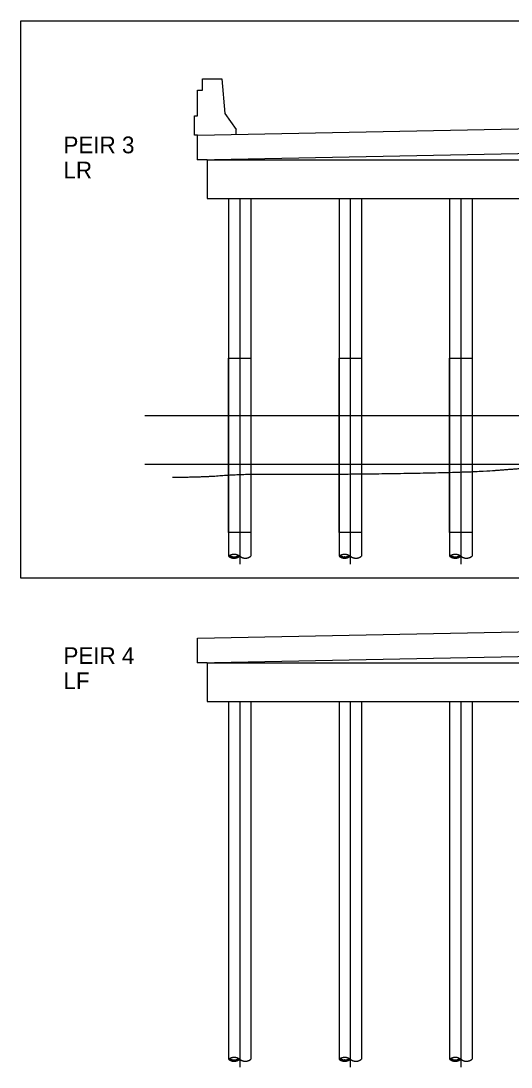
# Model space of a CAD drawing. Extents: x -8 to 159, y -47 to 10.
# Drawn here: x 49.8 to 75.3, y -47 to 7.4 of the extents above; entities that cross this region are included whole.
import ezdxf

# ---------------------------------------------------------------- set-up
doc = ezdxf.new("R2010")
doc.units = 0
for name, color, linetype in [('BR_P_Gen_Hatch', 7, 'Continuous'), ('BR_X_Gen_Ground_Slope', 7, 'Continuous'), ('BR_X_Rail_Object', 7, 'Continuous'), ('BR_X_Slab_Const_Joint', 7, 'Continuous'), ('BR_X_Slab_Object', 7, 'Continuous'), ('BR_X_Sub_Deep_Centerline', 7, 'Continuous'), ('BR_X_Sub_Object', 7, 'Continuous'), ('Default', 7, 'Continuous'), ('HY_P_Water_Edge', 7, 'Continuous')]:
    doc.layers.add(name, color=color, linetype=linetype)

msp = doc.modelspace()

# ---------------------------------------------------------------- linework, layer by layer
at = {"layer": 'BR_P_Gen_Hatch'}
for points in [[(60.566, -10.158), (61.733, -10.158), (61.733, -19.221), (60.566, -19.221)], [(66.316, -10.158), (67.483, -10.158), (67.483, -19.221), (66.316, -19.221)], [(72.066, -10.158), (73.233, -10.158), (73.233, -19.221), (72.066, -19.221)]]:
    msp.add_lwpolyline(points, close=True, dxfattribs=at)
at = {"layer": 'BR_X_Gen_Ground_Slope'}
msp.add_line((61.15, -16.221), (61.15, -19.221), dxfattribs=at)
msp.add_open_spline([(57.657, -16.344), (59.111, -16.344), (61.15, -16.188), (63.344, -16.188), (67.317, -16.188), (73.234, -16.084), (75.553, -15.906), (77.817, -15.746), (78.984, -15.688), (81.617, -15.814), (83.567, -15.688), (84.734, -15.688), (90.316, -15.589), (92.759, -15.688), (96.234, -15.688), (100.033, -15.777), (101.984, -15.688), (107.931, -15.427)], degree=2, dxfattribs=at)
at = {"layer": 'BR_X_Rail_Object'}
for p, q in [((59.212, 3.77), (59.212, 4.354)), ((59.212, 4.354), (60.212, 4.354)), ((60.212, 4.354), (60.379, 2.56)), ((58.962, 2.437), (58.962, 3.77)), ((58.962, 2.437), (58.962, 3.77)), ((58.962, 3.77), (59.212, 3.77)), ((58.795, 1.437), (58.795, 2.437)), ((58.795, 2.437), (58.962, 2.437)), ((60.379, 2.56), (60.962, 1.727)), ((60.962, 1.477), (60.962, 1.727)), ((58.962, 1.437), (58.795, 1.437))]:
    msp.add_line(p, q, dxfattribs=at)
at = {"layer": 'BR_X_Slab_Const_Joint'}
for p, q in [((59.462, 0.146), (103.087, 0.146)), ((59.462, -26), (103.087, -26))]:
    msp.add_line(p, q, dxfattribs=at)
at = {"layer": 'BR_X_Slab_Object'}
for p, q in [((58.962, 1.437), (84.317, 1.937)), ((58.962, 0.146), (58.962, 1.437)), ((58.962, 0.146), (84.317, 0.646)), ((59.462, 0.146), (58.962, 0.146)), ((58.962, -24.708), (84.317, -24.208)), ((58.962, -26), (58.962, -24.708)), ((58.962, -26), (84.317, -25.5)), ((59.462, -26), (58.962, -26))]:
    msp.add_line(p, q, dxfattribs=at)
at = {"layer": 'BR_X_Sub_Deep_Centerline'}
for p, q in [((61.15, -1.854), (61.15, -20.859)), ((66.9, -1.854), (66.9, -20.859)), ((72.65, -1.854), (72.65, -20.859)), ((61.15, -28), (61.15, -47.005)), ((66.9, -28), (66.9, -47.005)), ((72.65, -28), (72.65, -47.005))]:
    msp.add_line(p, q, dxfattribs=at)
at = {"layer": 'BR_X_Sub_Object'}
for p, q in [((59.462, 0.146), (59.462, -1.854)), ((59.462, -1.854), (103.087, -1.854)), ((60.566, -1.854), (60.566, -20.447)), ((61.733, -1.854), (61.733, -20.447)), ((66.316, -1.854), (66.316, -20.447)), ((67.483, -1.854), (67.483, -20.447)), ((72.066, -1.854), (72.066, -20.447)), ((73.233, -1.854), (73.233, -20.447)), ((59.462, -26), (59.462, -28)), ((59.462, -28), (103.087, -28)), ((60.566, -28), (60.566, -46.593)), ((61.733, -28), (61.733, -46.593)), ((66.316, -28), (66.316, -46.593)), ((67.483, -28), (67.483, -46.593)), ((72.066, -28), (72.066, -46.593)), ((73.233, -28), (73.233, -46.593))]:
    msp.add_line(p, q, dxfattribs=at)
for points in [[(60.566, -20.447), (60.624, -20.407), (60.736, -20.361), (60.817, -20.347), (60.859, -20.345), (60.887, -20.346), (60.936, -20.352), (60.976, -20.36), (61.003, -20.368), (61.047, -20.385), (61.082, -20.402), (61.11, -20.419), (61.124, -20.428), (61.139, -20.439), (61.15, -20.447), (61.169, -20.463), (61.183, -20.473), (61.194, -20.48), (61.207, -20.489), (61.231, -20.502), (61.26, -20.516), (61.277, -20.523), (61.306, -20.533), (61.338, -20.542), (61.353, -20.545), (61.375, -20.549), (61.396, -20.552), (61.42, -20.554), (61.44, -20.554), (61.481, -20.552), (61.513, -20.548), (61.545, -20.542), (61.569, -20.536), (61.593, -20.528), (61.612, -20.52), (61.633, -20.511), (61.656, -20.5), (61.673, -20.49), (61.692, -20.478), (61.713, -20.463), (61.721, -20.457), (61.733, -20.447)], [(60.566, -20.447), (60.581, -20.46), (60.602, -20.475), (60.623, -20.488), (60.645, -20.501), (60.661, -20.509), (60.686, -20.52), (60.71, -20.529), (60.737, -20.538), (60.767, -20.545), (60.79, -20.549), (60.81, -20.552), (60.83, -20.553), (60.863, -20.554), (60.892, -20.554), (60.913, -20.551), (60.939, -20.547), (60.976, -20.538), (61.005, -20.529), (61.032, -20.519), (61.055, -20.508), (61.071, -20.5), (61.094, -20.487), (61.113, -20.475), (61.127, -20.465), (61.136, -20.458), (61.15, -20.447)], [(60.628, -20.41), (60.647, -20.424), (60.671, -20.438), (60.684, -20.445), (60.699, -20.453), (60.72, -20.462), (60.741, -20.469), (60.755, -20.474), (60.78, -20.48), (60.794, -20.483), (60.814, -20.486), (60.836, -20.488), (60.861, -20.489), (60.854, -20.489), (60.872, -20.489), (60.885, -20.488), (60.908, -20.486), (60.937, -20.482), (60.954, -20.478), (60.975, -20.472), (60.989, -20.468), (61.009, -20.46), (61.02, -20.456), (61.029, -20.451), (61.039, -20.446), (61.052, -20.439), (61.063, -20.433), (61.08, -20.422), (61.086, -20.418), (61.096, -20.41)], [(66.316, -20.447), (66.374, -20.407), (66.486, -20.361), (66.567, -20.347), (66.609, -20.345), (66.637, -20.346), (66.686, -20.352), (66.726, -20.36), (66.753, -20.368), (66.797, -20.385), (66.832, -20.402), (66.86, -20.419), (66.874, -20.428), (66.889, -20.439), (66.9, -20.447), (66.919, -20.463), (66.933, -20.473), (66.944, -20.48), (66.957, -20.489), (66.981, -20.502), (67.01, -20.516), (67.027, -20.523), (67.056, -20.533), (67.088, -20.542), (67.103, -20.545), (67.125, -20.549), (67.146, -20.552), (67.17, -20.554), (67.19, -20.554), (67.231, -20.552), (67.263, -20.548), (67.295, -20.542), (67.319, -20.536), (67.343, -20.528), (67.362, -20.52), (67.383, -20.511), (67.406, -20.5), (67.423, -20.49), (67.442, -20.478), (67.463, -20.463), (67.471, -20.457), (67.483, -20.447)], [(66.316, -20.447), (66.331, -20.46), (66.352, -20.475), (66.373, -20.488), (66.395, -20.501), (66.411, -20.509), (66.436, -20.52), (66.46, -20.529), (66.487, -20.538), (66.517, -20.545), (66.54, -20.549), (66.56, -20.552), (66.58, -20.553), (66.613, -20.554), (66.642, -20.554), (66.663, -20.551), (66.689, -20.547), (66.726, -20.538), (66.755, -20.529), (66.782, -20.519), (66.805, -20.508), (66.821, -20.5), (66.844, -20.487), (66.863, -20.475), (66.877, -20.465), (66.886, -20.458), (66.9, -20.447)], [(66.378, -20.41), (66.397, -20.424), (66.421, -20.438), (66.434, -20.445), (66.449, -20.453), (66.47, -20.462), (66.491, -20.469), (66.505, -20.474), (66.53, -20.48), (66.544, -20.483), (66.564, -20.486), (66.586, -20.488), (66.611, -20.489), (66.604, -20.489), (66.622, -20.489), (66.635, -20.488), (66.658, -20.486), (66.687, -20.482), (66.704, -20.478), (66.725, -20.472), (66.739, -20.468), (66.759, -20.46), (66.77, -20.456), (66.779, -20.451), (66.789, -20.446), (66.802, -20.439), (66.813, -20.433), (66.83, -20.422), (66.836, -20.418), (66.846, -20.41)], [(72.066, -20.447), (72.124, -20.407), (72.236, -20.361), (72.317, -20.347), (72.359, -20.345), (72.387, -20.346), (72.436, -20.352), (72.476, -20.36), (72.503, -20.368), (72.547, -20.385), (72.582, -20.402), (72.61, -20.419), (72.624, -20.428), (72.639, -20.439), (72.65, -20.447), (72.669, -20.463), (72.683, -20.473), (72.694, -20.48), (72.707, -20.489), (72.731, -20.502), (72.76, -20.516), (72.777, -20.523), (72.806, -20.533), (72.838, -20.542), (72.853, -20.545), (72.875, -20.549), (72.896, -20.552), (72.92, -20.554), (72.94, -20.554), (72.981, -20.552), (73.013, -20.548), (73.045, -20.542), (73.069, -20.536), (73.093, -20.528), (73.112, -20.52), (73.133, -20.511), (73.156, -20.5), (73.173, -20.49), (73.192, -20.478), (73.213, -20.463), (73.221, -20.457), (73.233, -20.447)], [(72.066, -20.447), (72.081, -20.46), (72.102, -20.475), (72.123, -20.488), (72.145, -20.501), (72.161, -20.509), (72.186, -20.52), (72.21, -20.529), (72.237, -20.538), (72.267, -20.545), (72.29, -20.549), (72.31, -20.552), (72.33, -20.553), (72.363, -20.554), (72.392, -20.554), (72.413, -20.551), (72.439, -20.547), (72.476, -20.538), (72.505, -20.529), (72.532, -20.519), (72.555, -20.508), (72.571, -20.5), (72.594, -20.487), (72.613, -20.475), (72.627, -20.465), (72.636, -20.458), (72.65, -20.447)], [(72.128, -20.41), (72.147, -20.424), (72.171, -20.438), (72.184, -20.445), (72.199, -20.453), (72.22, -20.462), (72.241, -20.469), (72.255, -20.474), (72.28, -20.48), (72.294, -20.483), (72.314, -20.486), (72.336, -20.488), (72.361, -20.489), (72.354, -20.489), (72.372, -20.489), (72.385, -20.488), (72.408, -20.486), (72.437, -20.482), (72.454, -20.478), (72.475, -20.472), (72.489, -20.468), (72.509, -20.46), (72.52, -20.456), (72.529, -20.451), (72.539, -20.446), (72.552, -20.439), (72.563, -20.433), (72.58, -20.422), (72.586, -20.418), (72.596, -20.41)], [(60.566, -46.593), (60.624, -46.553), (60.736, -46.507), (60.817, -46.492), (60.859, -46.491), (60.887, -46.492), (60.936, -46.497), (60.976, -46.506), (61.003, -46.514), (61.047, -46.531), (61.082, -46.548), (61.11, -46.565), (61.124, -46.574), (61.139, -46.585), (61.15, -46.592), (61.169, -46.609), (61.183, -46.618), (61.194, -46.626), (61.207, -46.635), (61.231, -46.648), (61.26, -46.662), (61.277, -46.669), (61.306, -46.679), (61.338, -46.688), (61.353, -46.691), (61.375, -46.695), (61.396, -46.698), (61.42, -46.699), (61.44, -46.7), (61.481, -46.698), (61.513, -46.694), (61.545, -46.688), (61.569, -46.681), (61.593, -46.673), (61.612, -46.666), (61.633, -46.657), (61.656, -46.645), (61.673, -46.635), (61.692, -46.624), (61.713, -46.609), (61.721, -46.602), (61.733, -46.593)], [(60.566, -46.593), (60.581, -46.605), (60.602, -46.62), (60.623, -46.634), (60.645, -46.646), (60.661, -46.655), (60.686, -46.666), (60.71, -46.675), (60.737, -46.684), (60.767, -46.691), (60.79, -46.695), (60.81, -46.697), (60.83, -46.699), (60.863, -46.7), (60.892, -46.7), (60.913, -46.696), (60.939, -46.692), (60.976, -46.684), (61.005, -46.675), (61.032, -46.665), (61.055, -46.654), (61.071, -46.646), (61.094, -46.633), (61.113, -46.621), (61.127, -46.61), (61.136, -46.604), (61.15, -46.593)], [(60.628, -46.556), (60.647, -46.57), (60.671, -46.584), (60.684, -46.591), (60.699, -46.599), (60.72, -46.608), (60.741, -46.615), (60.755, -46.62), (60.78, -46.626), (60.794, -46.629), (60.814, -46.632), (60.836, -46.634), (60.861, -46.635), (60.854, -46.634), (60.872, -46.634), (60.885, -46.634), (60.908, -46.632), (60.937, -46.627), (60.954, -46.624), (60.975, -46.618), (60.989, -46.613), (61.009, -46.606), (61.02, -46.601), (61.029, -46.597), (61.039, -46.592), (61.052, -46.585), (61.063, -46.579), (61.08, -46.568), (61.086, -46.564), (61.096, -46.556)], [(66.316, -46.593), (66.374, -46.553), (66.486, -46.507), (66.567, -46.492), (66.609, -46.491), (66.637, -46.492), (66.686, -46.497), (66.726, -46.506), (66.753, -46.514), (66.797, -46.531), (66.832, -46.548), (66.86, -46.565), (66.874, -46.574), (66.889, -46.585), (66.9, -46.592), (66.919, -46.609), (66.933, -46.618), (66.944, -46.626), (66.957, -46.635), (66.981, -46.648), (67.01, -46.662), (67.027, -46.669), (67.056, -46.679), (67.088, -46.688), (67.103, -46.691), (67.125, -46.695), (67.146, -46.698), (67.17, -46.699), (67.19, -46.7), (67.231, -46.698), (67.263, -46.694), (67.295, -46.688), (67.319, -46.681), (67.343, -46.673), (67.362, -46.666), (67.383, -46.657), (67.406, -46.645), (67.423, -46.635), (67.442, -46.624), (67.463, -46.609), (67.471, -46.602), (67.483, -46.593)], [(66.316, -46.593), (66.331, -46.605), (66.352, -46.62), (66.373, -46.634), (66.395, -46.646), (66.411, -46.655), (66.436, -46.666), (66.46, -46.675), (66.487, -46.684), (66.517, -46.691), (66.54, -46.695), (66.56, -46.697), (66.58, -46.699), (66.613, -46.7), (66.642, -46.7), (66.663, -46.696), (66.689, -46.692), (66.726, -46.684), (66.755, -46.675), (66.782, -46.665), (66.805, -46.654), (66.821, -46.646), (66.844, -46.633), (66.863, -46.621), (66.877, -46.61), (66.886, -46.604), (66.9, -46.593)], [(66.378, -46.556), (66.397, -46.57), (66.421, -46.584), (66.434, -46.591), (66.449, -46.599), (66.47, -46.608), (66.491, -46.615), (66.505, -46.62), (66.53, -46.626), (66.544, -46.629), (66.564, -46.632), (66.586, -46.634), (66.611, -46.635), (66.604, -46.634), (66.622, -46.634), (66.635, -46.634), (66.658, -46.632), (66.687, -46.627), (66.704, -46.624), (66.725, -46.618), (66.739, -46.613), (66.759, -46.606), (66.77, -46.601), (66.779, -46.597), (66.789, -46.592), (66.802, -46.585), (66.813, -46.579), (66.83, -46.568), (66.836, -46.564), (66.846, -46.556)], [(72.066, -46.593), (72.124, -46.553), (72.236, -46.507), (72.317, -46.492), (72.359, -46.491), (72.387, -46.492), (72.436, -46.497), (72.476, -46.506), (72.503, -46.514), (72.547, -46.531), (72.582, -46.548), (72.61, -46.565), (72.624, -46.574), (72.639, -46.585), (72.65, -46.592), (72.669, -46.609), (72.683, -46.618), (72.694, -46.626), (72.707, -46.635), (72.731, -46.648), (72.76, -46.662), (72.777, -46.669), (72.806, -46.679), (72.838, -46.688), (72.853, -46.691), (72.875, -46.695), (72.896, -46.698), (72.92, -46.699), (72.94, -46.7), (72.981, -46.698), (73.013, -46.694), (73.045, -46.688), (73.069, -46.681), (73.093, -46.673), (73.112, -46.666), (73.133, -46.657), (73.156, -46.645), (73.173, -46.635), (73.192, -46.624), (73.213, -46.609), (73.221, -46.602), (73.233, -46.593)], [(72.066, -46.593), (72.081, -46.605), (72.102, -46.62), (72.123, -46.634), (72.145, -46.646), (72.161, -46.655), (72.186, -46.666), (72.21, -46.675), (72.237, -46.684), (72.267, -46.691), (72.29, -46.695), (72.31, -46.697), (72.33, -46.699), (72.363, -46.7), (72.392, -46.7), (72.413, -46.696), (72.439, -46.692), (72.476, -46.684), (72.505, -46.675), (72.532, -46.665), (72.555, -46.654), (72.571, -46.646), (72.594, -46.633), (72.613, -46.621), (72.627, -46.61), (72.636, -46.604), (72.65, -46.593)], [(72.128, -46.556), (72.147, -46.57), (72.171, -46.584), (72.184, -46.591), (72.199, -46.599), (72.22, -46.608), (72.241, -46.615), (72.255, -46.62), (72.28, -46.626), (72.294, -46.629), (72.314, -46.632), (72.336, -46.634), (72.361, -46.635), (72.354, -46.634), (72.372, -46.634), (72.385, -46.634), (72.408, -46.632), (72.437, -46.627), (72.454, -46.624), (72.475, -46.618), (72.489, -46.613), (72.509, -46.606), (72.52, -46.601), (72.529, -46.597), (72.539, -46.592), (72.552, -46.585), (72.563, -46.579), (72.58, -46.568), (72.586, -46.564), (72.596, -46.556)]]:
    msp.add_open_spline(points, degree=2, dxfattribs=at)
at = {"layer": 'Default'}
msp.add_lwpolyline([(49.771, 7.367), (108.797, 7.367), (108.797, -21.588), (49.771, -21.588)], close=True, dxfattribs=at)
at = {"layer": 'HY_P_Water_Edge'}
for p, q in [((104.807, -13.158), (56.22, -13.158)), ((104.807, -15.688), (56.22, -15.688))]:
    msp.add_line(p, q, dxfattribs=at)

# ---------------------------------------------------------------- texts
at = {"layer": 'BR_X_Slab_Object'}
for s, p in [('PEIR 3', (51.983, 0.487)), ('LR', (51.983, -0.82)), ('PEIR 4', (51.983, -26.056)), ('LF', (51.983, -27.363))]:
    msp.add_text(s, height=0.8714, dxfattribs=at).set_placement(p)

doc.saveas('drawing.dxf')
